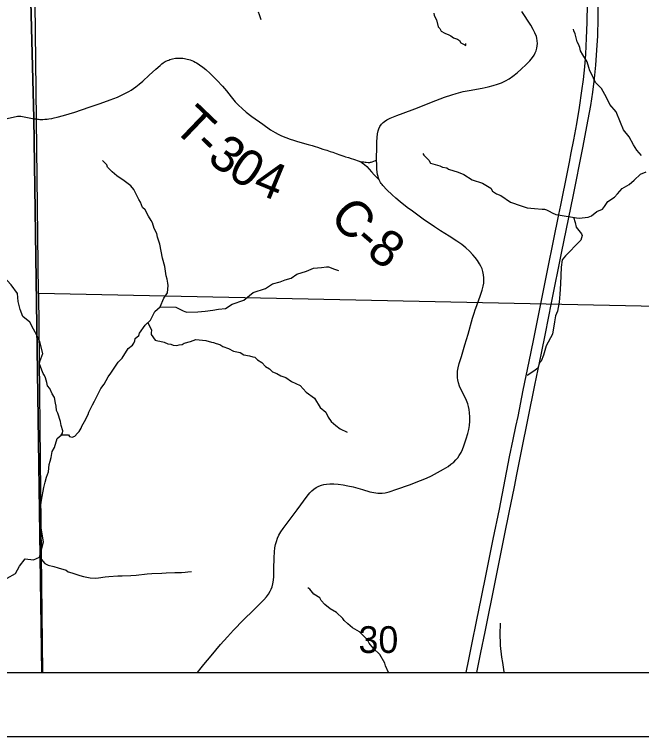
# Model space of a CAD drawing. Extents: x 0 to 34, y 0 to 22.
# Drawn here: x 4.535 to 5.516, y 14 to 15.129 of the extents above; entities that cross this region are included whole.
import ezdxf

# ---------------------------------------------------------------- set-up
doc = ezdxf.new("R2010")
doc.units = 0
for name, color, linetype in [('GM_X_County_Road', 7, 'Continuous'), ('GM_X_County_Road_Text', 7, 'Continuous'), ('GM_X_Interstate_Route', 7, 'Continuous'), ('GM_X_Minor_River', 7, 'Continuous'), ('GM_X_Rail_Line', 7, 'Continuous'), ('GM_X_Section', 7, 'Continuous'), ('GM_X_Section_Text', 7, 'Continuous'), ('GM_X_State_Shield', 7, 'Continuous'), ('GM_X_Township_Road', 7, 'Continuous'), ('GM_X_Township_Road_Text', 7, 'Continuous'), ('SH_Cut_Line', 7, 'Continuous'), ('SH_Data', 7, 'Continuous')]:
    doc.layers.add(name, color=color, linetype=linetype)

msp = doc.modelspace()

# ---------------------------------------------------------------- linework, layer by layer
at = {"layer": 'GM_X_County_Road'}
for points in [[(5.1016, 14.9018), (5.1016, 14.9062), (5.1017, 14.9192), (5.1018, 14.9298), (5.1022, 14.9366), (5.1029, 14.9423), (5.104, 14.9472), (5.105, 14.9503), (5.1066, 14.9537), (5.1091, 14.9575), (5.1117, 14.9603), (5.1137, 14.9619), (5.1174, 14.9644), (5.1225, 14.9669), (5.133, 14.9711), (5.1569, 14.9799), (5.1656, 14.9832), (5.1743, 14.9866), (5.1939, 14.9944), (5.2078, 14.9998), (5.219, 15.0037), (5.2261, 15.0058), (5.237, 15.0085), (5.2462, 15.0104), (5.2664, 15.0141), (5.2761, 15.016), (5.2839, 15.018), (5.2904, 15.02), (5.2967, 15.0224), (5.3028, 15.0253), (5.3086, 15.0287), (5.3147, 15.0328), (5.3211, 15.0378), (5.3276, 15.0434), (5.3352, 15.0507), (5.3412, 15.0569), (5.3451, 15.0616), (5.3478, 15.0657), (5.3495, 15.0689), (5.3509, 15.0722), (5.3521, 15.0763), (5.3527, 15.0799), (5.3529, 15.0835), (5.3527, 15.0877), (5.352, 15.0919), (5.3513, 15.0948), (5.3489, 15.1004), (5.3464, 15.1054), (5.3424, 15.1123), (5.3288, 15.1339)], [(5.1054, 14.8708), (5.1046, 14.8733), (5.1038, 14.8756), (5.103, 14.8788), (5.1024, 14.8825), (5.102, 14.887), (5.1017, 14.8938), (5.1016, 14.9018)], [(4.8213, 14.1), (4.8271, 14.1073), (4.8315, 14.1125), (4.843, 14.1264), (4.8577, 14.144), (4.8684, 14.156), (4.878, 14.1665), (4.8937, 14.1823), (4.9091, 14.1975), (4.9251, 14.2139), (4.9292, 14.2185), (4.9324, 14.2229), (4.9349, 14.2271), (4.9366, 14.2303), (4.9381, 14.2343), (4.9394, 14.239), (4.9404, 14.2444), (4.9409, 14.2505), (4.9411, 14.2623), (4.9413, 14.2797), (4.9418, 14.2891), (4.9425, 14.2953), (4.9434, 14.3002), (4.9448, 14.3051), (4.9468, 14.3104), (4.9489, 14.315), (4.9517, 14.3199), (4.9552, 14.3251), (4.9635, 14.336), (4.968, 14.342), (4.9772, 14.3545), (4.993, 14.376), (4.997, 14.3809), (5.0001, 14.3841), (5.0034, 14.387), (5.0071, 14.3895), (5.0111, 14.3915), (5.0152, 14.3931), (5.0188, 14.3941), (5.0232, 14.3948), (5.0282, 14.3953), (5.0344, 14.3953), (5.0413, 14.3948), (5.0493, 14.3937), (5.0567, 14.3923), (5.0651, 14.3903), (5.0795, 14.3862), (5.0908, 14.3829), (5.0974, 14.3814), (5.1034, 14.3806), (5.1064, 14.3804), (5.1101, 14.3805), (5.1149, 14.3812), (5.1214, 14.3829), (5.1332, 14.3867), (5.1531, 14.3938), (5.1699, 14.4002), (5.1796, 14.4042), (5.1875, 14.4078), (5.1968, 14.4127), (5.206, 14.4179), (5.2133, 14.4225), (5.2178, 14.4257), (5.222, 14.4292), (5.2255, 14.4326), (5.2283, 14.4359), (5.2308, 14.4394), (5.2335, 14.4441), (5.2359, 14.4491), (5.2381, 14.4548), (5.2417, 14.4654), (5.2441, 14.4737), (5.2456, 14.4803), (5.2465, 14.4864), (5.247, 14.4931), (5.2472, 14.4999), (5.2469, 14.506), (5.2463, 14.5115), (5.2453, 14.5163), (5.2442, 14.5204), (5.2421, 14.5255), (5.2395, 14.5311), (5.2337, 14.5421), (5.2312, 14.5479), (5.2294, 14.5533), (5.2285, 14.5576), (5.228, 14.5608), (5.2278, 14.5658), (5.2282, 14.5715), (5.2291, 14.5764), (5.2308, 14.5831), (5.2343, 14.5945), (5.2397, 14.6123), (5.2445, 14.629), (5.2515, 14.6541), (5.2539, 14.6619), (5.2556, 14.6672), (5.2581, 14.6742), (5.2639, 14.69), (5.2666, 14.6982), (5.2682, 14.7041), (5.2689, 14.7089), (5.2693, 14.7132), (5.2693, 14.7174), (5.2687, 14.7222), (5.2677, 14.727), (5.2663, 14.7316), (5.2646, 14.7355), (5.2626, 14.7393), (5.2593, 14.7445), (5.2555, 14.7493), (5.2519, 14.7535), (5.2467, 14.7588), (5.2408, 14.7642), (5.2345, 14.7692), (5.2269, 14.7746), (5.2149, 14.7823), (5.2012, 14.7908), (5.1919, 14.797), (5.1745, 14.8091), (5.1574, 14.8215), (5.1494, 14.8274), (5.1382, 14.8363), (5.1315, 14.8419), (5.1259, 14.8469), (5.1174, 14.8551), (5.1114, 14.8615), (5.1101, 14.8631), (5.1089, 14.8648), (5.1078, 14.8664), (5.1066, 14.8685), (5.1054, 14.8708)]]:
    msp.add_lwpolyline(points, dxfattribs=at)
at = {"layer": 'GM_X_Interstate_Route'}
for points in [[(5.2415, 14.1), (5.2456, 14.1207), (5.2503, 14.1438), (5.2584, 14.1827), (5.2651, 14.2156), (5.2732, 14.2564), (5.2839, 14.3088), (5.2934, 14.3556), (5.3094, 14.4373), (5.315, 14.4647), (5.3192, 14.4847), (5.3226, 14.5005), (5.3308, 14.5414), (5.34, 14.5864), (5.3466, 14.6193), (5.3492, 14.6321), (5.3577, 14.6741), (5.3692, 14.7314), (5.378, 14.7752), (5.3863, 14.8166), (5.3894, 14.8312), (5.3997, 14.8823), (5.4029, 14.8981), (5.4058, 14.9128), (5.4099, 14.9329), (5.4145, 14.9579), (5.4188, 14.9837), (5.4225, 15.0095), (5.4248, 15.0274), (5.4268, 15.0472), (5.4284, 15.067), (5.4298, 15.0919), (5.4307, 15.1167), (5.4313, 15.1465)], [(5.2581, 14.1), (5.2644, 14.1313), (5.271, 14.1636), (5.2867, 14.2416), (5.3017, 14.3146), (5.3088, 14.3505), (5.3169, 14.3907), (5.3208, 14.4096), (5.3281, 14.4461), (5.3385, 14.4979), (5.3489, 14.5497), (5.3591, 14.5996), (5.3653, 14.6301), (5.3751, 14.6782), (5.3913, 14.7585), (5.4086, 14.8444), (5.4237, 14.9205), (5.4324, 14.965), (5.4362, 14.987), (5.4394, 15.0079), (5.4421, 15.0288), (5.4442, 15.0498), (5.446, 15.0733), (5.4471, 15.0956), (5.4477, 15.1229), (5.4477, 15.1465)]]:
    msp.add_lwpolyline(points, dxfattribs=at)
at = {"layer": 'GM_X_Minor_River'}
for points in [[(4.9163, 15.1332), (4.9179, 15.129), (4.9207, 15.1211)], [(5.1912, 15.1311), (5.1916, 15.1273), (5.1952, 15.1205), (5.198, 15.1099), (5.2003, 15.1073), (5.2023, 15.1031), (5.2081, 15.0998), (5.2142, 15.0972)], [(5.2142, 15.0972), (5.2176, 15.0958), (5.2218, 15.0924), (5.228, 15.0906), (5.231, 15.0884), (5.233, 15.085), (5.2364, 15.0831), (5.241, 15.0806), (5.241, 15.0836)], [(5.5158, 14.9086), (5.5081, 14.9172), (5.503, 14.9251), (5.4963, 14.9379), (5.4874, 14.9488), (5.4827, 14.9601), (5.4759, 14.9771), (5.4662, 14.9884), (5.4611, 14.9993), (5.4533, 15.0136), (5.4436, 15.023), (5.4405, 15.0294), (5.4377, 15.0365), (5.4349, 15.0411), (5.4333, 15.0464), (5.4305, 15.055), (5.4239, 15.066), (5.42, 15.0724), (5.4191, 15.0777), (5.4171, 15.0829), (5.4152, 15.0863), (5.4119, 15.0988), (5.4096, 15.1037), (5.4091, 15.1064)], [(5.1737, 14.9116), (5.1753, 14.9089), (5.1834, 14.9015), (5.1858, 14.8966), (5.2006, 14.8922), (5.2045, 14.8904), (5.2113, 14.8894), (5.214, 14.8871), (5.2289, 14.8828), (5.2377, 14.8788), (5.2507, 14.8706), (5.2668, 14.8652), (5.2802, 14.8574), (5.2826, 14.8529), (5.2891, 14.8488), (5.2956, 14.8459), (5.311, 14.8355), (5.3274, 14.83), (5.3369, 14.8268), (5.3483, 14.8258), (5.3605, 14.8249), (5.3639, 14.8245), (5.3673, 14.8234), (5.3712, 14.8216), (5.3762, 14.819), (5.3815, 14.8161), (5.3853, 14.8157), (5.3979, 14.814), (5.4078, 14.8123), (5.4142, 14.8113), (5.4184, 14.8106), (5.423, 14.811), (5.4324, 14.8123), (5.4377, 14.8143), (5.4456, 14.8209), (5.4546, 14.8248), (5.458, 14.8287), (5.4632, 14.8367), (5.4733, 14.8433), (5.4781, 14.8487), (5.4852, 14.8568), (5.4965, 14.8635), (5.504, 14.87), (5.514, 14.8793), (5.5231, 14.8829)], [(4.6078, 14.4718), (4.6199, 14.4716), (4.6215, 14.469), (4.6257, 14.4683), (4.6298, 14.4695), (4.6339, 14.4745), (4.6365, 14.4768), (4.6398, 14.4822), (4.6409, 14.4853), (4.645, 14.4925), (4.6505, 14.5036), (4.6515, 14.5075), (4.6574, 14.5189), (4.6607, 14.5247), (4.6703, 14.5442), (4.6755, 14.5511), (4.6821, 14.5627), (4.6862, 14.5684), (4.6976, 14.5857), (4.7036, 14.5919), (4.7132, 14.6068), (4.72, 14.6119), (4.7222, 14.615), (4.7236, 14.6188), (4.7243, 14.6226), (4.73, 14.6272), (4.7307, 14.6307), (4.7399, 14.6433), (4.7481, 14.6511), (4.7547, 14.6645), (4.7633, 14.6722), (4.7688, 14.6856), (4.7744, 14.694), (4.7757, 14.7051), (4.7752, 14.7092), (4.774, 14.7153), (4.7728, 14.7202), (4.7706, 14.735), (4.7666, 14.7479), (4.7624, 14.7698), (4.7588, 14.7808), (4.7579, 14.7865), (4.754, 14.7944), (4.7512, 14.8031), (4.7492, 14.8069), (4.7449, 14.8136), (4.7395, 14.8238), (4.7356, 14.8275), (4.7324, 14.8355), (4.7297, 14.84), (4.7218, 14.8554), (4.7172, 14.8611), (4.7068, 14.8689), (4.6953, 14.877), (4.6879, 14.883), (4.681, 14.8905), (4.6798, 14.8939), (4.6728, 14.901)], [(4.5707, 14.6266), (4.565, 14.6368), (4.5592, 14.6481), (4.5485, 14.6567), (4.5442, 14.6676), (4.541, 14.6801), (4.5401, 14.693), (4.5301, 14.7066), (4.5175, 14.7197), (4.5071, 14.7325), (4.4982, 14.7453), (4.4924, 14.7555), (4.4881, 14.766), (4.485, 14.7759), (4.4792, 14.7883), (4.4749, 14.7985), (4.4732, 14.8122)], [(5.4093, 14.8121), (5.4117, 14.8036), (5.4134, 14.7964), (5.4219, 14.7863), (5.4227, 14.7837), (5.4209, 14.776), (5.4112, 14.7668), (5.4045, 14.7594), (5.3967, 14.7517), (5.3915, 14.7456), (5.3898, 14.7338), (5.3891, 14.7079), (5.3882, 14.6919), (5.3869, 14.6794), (5.3841, 14.6653), (5.3812, 14.658), (5.3795, 14.6485), (5.3764, 14.6294), (5.3668, 14.6111), (5.3625, 14.5966), (5.3589, 14.587), (5.3563, 14.5843), (5.3534, 14.5759), (5.3474, 14.5716), (5.3369, 14.5646)], [(4.7636, 14.6722), (4.7876, 14.6715), (4.7991, 14.6656), (4.8018, 14.6648), (4.8049, 14.6637), (4.8223, 14.664), (4.8333, 14.6653), (4.8454, 14.6667), (4.8541, 14.6683), (4.8655, 14.6696), (4.8756, 14.6759), (4.8938, 14.6822), (4.9087, 14.6943), (4.9276, 14.7006), (4.9389, 14.708), (4.9506, 14.7109), (4.9585, 14.7144), (4.9679, 14.7168), (4.9766, 14.7231), (4.992, 14.7279), (5.003, 14.7322), (5.0155, 14.7336), (5.0231, 14.7344), (5.0265, 14.7345), (5.0356, 14.7308), (5.0421, 14.729)], [(4.7441, 14.6473), (4.7495, 14.6355), (4.7489, 14.6313), (4.7489, 14.6287), (4.7555, 14.62), (4.7597, 14.619), (4.7628, 14.6182), (4.7696, 14.6165), (4.775, 14.6143), (4.7799, 14.6136), (4.7834, 14.6121), (4.7894, 14.6115), (4.7928, 14.6123), (4.7974, 14.6131), (4.8008, 14.6154), (4.8106, 14.6179), (4.8189, 14.6207), (4.8295, 14.6201), (4.8345, 14.6194), (4.8433, 14.6169), (4.8467, 14.6162), (4.8509, 14.6147), (4.8562, 14.6133), (4.8612, 14.6099), (4.87, 14.607), (4.8777, 14.6026), (4.888, 14.6005), (4.8941, 14.5971), (4.9028, 14.5954), (4.9078, 14.5939), (4.9112, 14.5932), (4.9155, 14.5891), (4.922, 14.5847), (4.9278, 14.5787), (4.9343, 14.575), (4.939, 14.5705), (4.9458, 14.5679), (4.9516, 14.5642), (4.9596, 14.5617), (4.9685, 14.555), (4.9822, 14.5488), (4.9915, 14.5383), (5.0042, 14.529), (5.0132, 14.5143), (5.0224, 14.5072), (5.026, 14.4993), (5.0303, 14.4925), (5.0376, 14.4862), (5.0445, 14.4814), (5.0556, 14.4758)], [(4.581, 14.3043), (4.577, 14.326), (4.577, 14.3294), (4.5765, 14.333), (4.5752, 14.338), (4.576, 14.3516), (4.5763, 14.3581), (4.5776, 14.3699), (4.5811, 14.3897), (4.5836, 14.3977), (4.5857, 14.4057), (4.5886, 14.4141), (4.5896, 14.4256), (4.591, 14.4305), (4.5928, 14.4366), (4.5945, 14.4458), (4.5978, 14.4519), (4.6022, 14.466), (4.6085, 14.4714), (4.6107, 14.4745), (4.6111, 14.4779), (4.6086, 14.4863), (4.6074, 14.4927), (4.6034, 14.5056), (4.601, 14.5101), (4.6005, 14.5165), (4.5997, 14.5215), (4.598, 14.5302), (4.5945, 14.5358), (4.5909, 14.5445), (4.5871, 14.5486), (4.5858, 14.5535), (4.5838, 14.5611), (4.5822, 14.5645), (4.5803, 14.5679), (4.5791, 14.5705), (4.5767, 14.5773), (4.5747, 14.5826), (4.575, 14.5864), (4.5797, 14.5988), (4.575, 14.6171), (4.5707, 14.6266)], [(4.5746, 14.2807), (4.581, 14.3043)], [(4.524, 14.2478), (4.5372, 14.2552), (4.5435, 14.2663), (4.5521, 14.2777), (4.5653, 14.2764), (4.5746, 14.2807)], [(4.5746, 14.2807), (4.5828, 14.2708), (4.5881, 14.2682), (4.5969, 14.2661), (4.6038, 14.2636), (4.6164, 14.26), (4.6194, 14.2577), (4.6252, 14.2559), (4.6374, 14.2519), (4.6431, 14.2501), (4.6538, 14.2484), (4.6617, 14.2478), (4.6667, 14.2482), (4.6773, 14.2499), (4.683, 14.2504), (4.697, 14.2513), (4.7038, 14.2515), (4.7175, 14.2521), (4.7258, 14.2526), (4.7429, 14.2544), (4.7504, 14.2549), (4.7656, 14.2555), (4.7724, 14.256), (4.7861, 14.2566), (4.7963, 14.2567), (4.8024, 14.2572), (4.8066, 14.2576), (4.8119, 14.2581)], [(5.12, 14.1), (5.1155, 14.1105), (5.1143, 14.1147), (5.1068, 14.1283), (5.0968, 14.1376), (5.0898, 14.1458), (5.0874, 14.1511), (5.0747, 14.1638), (5.064, 14.1701), (5.0566, 14.1765), (5.0509, 14.1813), (5.0489, 14.1847), (5.0389, 14.1941), (5.0289, 14.1996), (5.0208, 14.2067), (5.0146, 14.2127), (5.0127, 14.2168), (5.0034, 14.2227), (4.9972, 14.2306), (4.9938, 14.2325)], [(5.301, 14.1), (5.3009, 14.1013), (5.2991, 14.1157), (5.2971, 14.1244), (5.2952, 14.1426), (5.2951, 14.1502), (5.2946, 14.1548), (5.2945, 14.1612), (5.2948, 14.1665), (5.2951, 14.1704), (5.2954, 14.1745), (5.2954, 14.1772)]]:
    msp.add_lwpolyline(points, dxfattribs=at)
at = {"layer": 'GM_X_Rail_Line'}
msp.add_lwpolyline([(2.1, 18.7171), (2.1, 14.1), (4.5781, 14.1), (4.5658, 14.9668), (4.5509, 15.5331), (4.5478, 16.582), (4.5489, 17.6578), (4.5474, 17.7028), (4.5429, 17.9404), (4.5419, 17.9684), (4.5402, 18.2851), (4.5408, 18.3763), (4.5397, 18.3961), (4.5397, 18.4045), (4.5399, 18.4424), (4.5403, 18.5054), (4.5462, 18.6416), (3.8456, 18.6615), (3.8442, 18.6615), (2.9234, 18.6945), (2.9222, 18.6946), (2.7892, 18.6993), (2.7864, 18.6994)], close=True, dxfattribs=at)
msp.add_lwpolyline([(7.149, 16.6283), (5.9824, 16.6436), (5.6594, 16.6485), (5.6614, 16.7344), (5.6628, 16.7878), (5.6628, 16.7899), (5.6656, 16.9939), (5.6743, 17.6274), (5.3403, 17.635), (5.2052, 17.638), (4.9797, 17.6498), (4.9624, 17.6496), (4.8158, 17.6467), (4.5489, 17.6578), (4.5478, 16.582), (4.5509, 15.5331), (4.5658, 14.9668), (4.5781, 14.1), (8.76, 14.1)], dxfattribs=at)
at = {"layer": 'GM_X_Section'}
msp.add_lwpolyline([(4.5625, 15.6671), (5.6397, 15.6496), (5.6391, 14.6704), (4.5729, 14.6928), (4.5655, 15.3289)], close=True, dxfattribs=at)
at = {"layer": 'GM_X_State_Shield'}
msp.add_lwpolyline([(4.5791, 14.1), (5.6342, 14.1), (5.6391, 14.6704), (4.5729, 14.6928), (4.5765, 14.3313)], close=True, dxfattribs=at)
at = {"layer": 'GM_X_Township_Road'}
for points in [[(4.566, 14.9662), (4.5679, 14.966), (4.5696, 14.9657), (4.5713, 14.9655), (4.5731, 14.9653), (4.5749, 14.9651), (4.5767, 14.965), (4.5785, 14.9649), (4.58, 14.965), (4.5831, 14.9652), (4.5863, 14.9656), (4.5893, 14.966), (4.5937, 14.9667), (4.5977, 14.9676), (4.6022, 14.9685), (4.6123, 14.9713), (4.6296, 14.9766), (4.652, 14.9841), (4.6696, 14.9901), (4.6848, 14.9954), (4.6964, 15), (4.7049, 15.0038), (4.708, 15.0054), (4.711, 15.0069), (4.7144, 15.0089), (4.7179, 15.011), (4.7252, 15.0158), (4.7306, 15.0199), (4.7363, 15.0247), (4.7462, 15.0341), (4.7562, 15.0435), (4.7631, 15.0496), (4.7658, 15.0517), (4.768, 15.0534), (4.7696, 15.0545), (4.7712, 15.0554), (4.7745, 15.0571), (4.7765, 15.0579), (4.7785, 15.0586), (4.7827, 15.0597), (4.7874, 15.0606), (4.7897, 15.0609), (4.792, 15.061), (4.7963, 15.0609), (4.7985, 15.0607), (4.8011, 15.0605), (4.8032, 15.06), (4.8053, 15.0595), (4.8079, 15.0588), (4.81, 15.0581), (4.8126, 15.0572), (4.8152, 15.0561), (4.8179, 15.0548), (4.8201, 15.0536), (4.8228, 15.0519), (4.8248, 15.0506), (4.8298, 15.047), (4.8347, 15.0431), (4.8415, 15.0368), (4.8515, 15.0266), (4.8604, 15.017), (4.8668, 15.0095), (4.8742, 15.0003), (4.8806, 14.9927), (4.8857, 14.9873), (4.8911, 14.9822), (4.8977, 14.9766), (4.9065, 14.9697), (4.9236, 14.9574), (4.9359, 14.9489), (4.9392, 14.9468), (4.943, 14.9445), (4.9478, 14.9419), (4.953, 14.9394), (4.9596, 14.9366), (4.9664, 14.9343), (4.9714, 14.9328), (4.978, 14.9307), (4.9943, 14.926), (5.0008, 14.9241), (5.0053, 14.9227), (5.0093, 14.9214), (5.0174, 14.9187), (5.0235, 14.9167), (5.0287, 14.9149), (5.0329, 14.9136), (5.0381, 14.9117), (5.044, 14.9096), (5.0469, 14.9086), (5.0502, 14.9076), (5.0529, 14.9067), (5.0574, 14.9053), (5.0616, 14.904), (5.0653, 14.9029), (5.0686, 14.9018), (5.0712, 14.9009), (5.0743, 14.8995)], [(4.5191, 14.9656), (4.54, 14.9702), (4.5451, 14.9702), (4.566, 14.9662)], [(5.0743, 14.8995), (5.0763, 14.8992), (5.0783, 14.8989), (5.0801, 14.8987), (5.0818, 14.8985), (5.0835, 14.8983), (5.0853, 14.8982), (5.0884, 14.8979), (5.0897, 14.8978), (5.091, 14.8978), (5.092, 14.898), (5.093, 14.8982), (5.0946, 14.8986), (5.0974, 14.8999), (5.0999, 14.901), (5.1016, 14.9018)], [(5.0743, 14.8995), (5.0752, 14.8991), (5.079, 14.897), (5.0825, 14.8945), (5.0862, 14.8912), (5.0901, 14.8872), (5.0936, 14.8831), (5.0979, 14.8784), (5.1007, 14.8755), (5.1026, 14.8735), (5.1054, 14.8708)]]:
    msp.add_lwpolyline(points, dxfattribs=at)
at = {"layer": 'SH_Cut_Line'}
for points in [[(2.1, 14.1), (4.5781, 14.1), (4.5658, 14.9668), (4.5509, 15.5331), (4.5478, 16.582), (4.5489, 17.6578), (4.8158, 17.6467), (4.9624, 17.6496), (4.9797, 17.6498), (5.2052, 17.638), (5.3403, 17.635), (5.6743, 17.6274), (5.6656, 16.9939), (5.6628, 16.7899), (5.6628, 16.7878), (5.6614, 16.7344), (5.6594, 16.6485), (5.9824, 16.6436), (7.149, 16.6283)], [(7.149, 16.6283), (5.9824, 16.6436), (5.6594, 16.6485), (5.6614, 16.7344), (5.6628, 16.7878), (5.6628, 16.7899), (5.6656, 16.9939), (5.6743, 17.6274), (5.3403, 17.635), (5.2052, 17.638), (4.9797, 17.6498), (4.9624, 17.6496), (4.8158, 17.6467), (4.5489, 17.6578), (4.5478, 16.582), (4.5509, 15.5331), (4.5658, 14.9668), (4.5781, 14.1), (8.9, 14.1)]]:
    msp.add_lwpolyline(points, dxfattribs=at)
at = {"layer": 'SH_Data'}
for p, q in [((2.1, 14.1), (8.9, 14.1)), ((2, 14), (9, 14))]:
    msp.add_line(p, q, dxfattribs=at)

# ---------------------------------------------------------------- texts
at = {"layer": 'GM_X_County_Road_Text'}
for s, rotation, p in [('C', 312.1424, (5.0261, 14.8116)), ('-', 318.9302, (5.0627, 14.7718)), ('8', 322.8527, (5.0836, 14.7538))]:
    msp.add_text(s, height=0.0568, rotation=rotation, dxfattribs=at).set_placement(p)
at = {"layer": 'GM_X_Section_Text'}
msp.add_text('30', height=0.04186, rotation=0, dxfattribs=at).set_placement((5.0732, 14.1307))
at = {"layer": 'GM_X_Township_Road_Text'}
for s, rotation, p in [('T', 316.279, (4.7814, 14.9511)), ('-', 316.1315, (4.8121, 14.9218)), ('3', 323.0944, (4.8347, 14.9007)), ('0', 327.0701, (4.8662, 14.8772)), ('4', 337.537, (4.9056, 14.853))]:
    msp.add_text(s, height=0.0568, rotation=rotation, dxfattribs=at).set_placement(p)

doc.saveas('drawing.dxf')
